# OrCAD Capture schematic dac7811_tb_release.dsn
size A
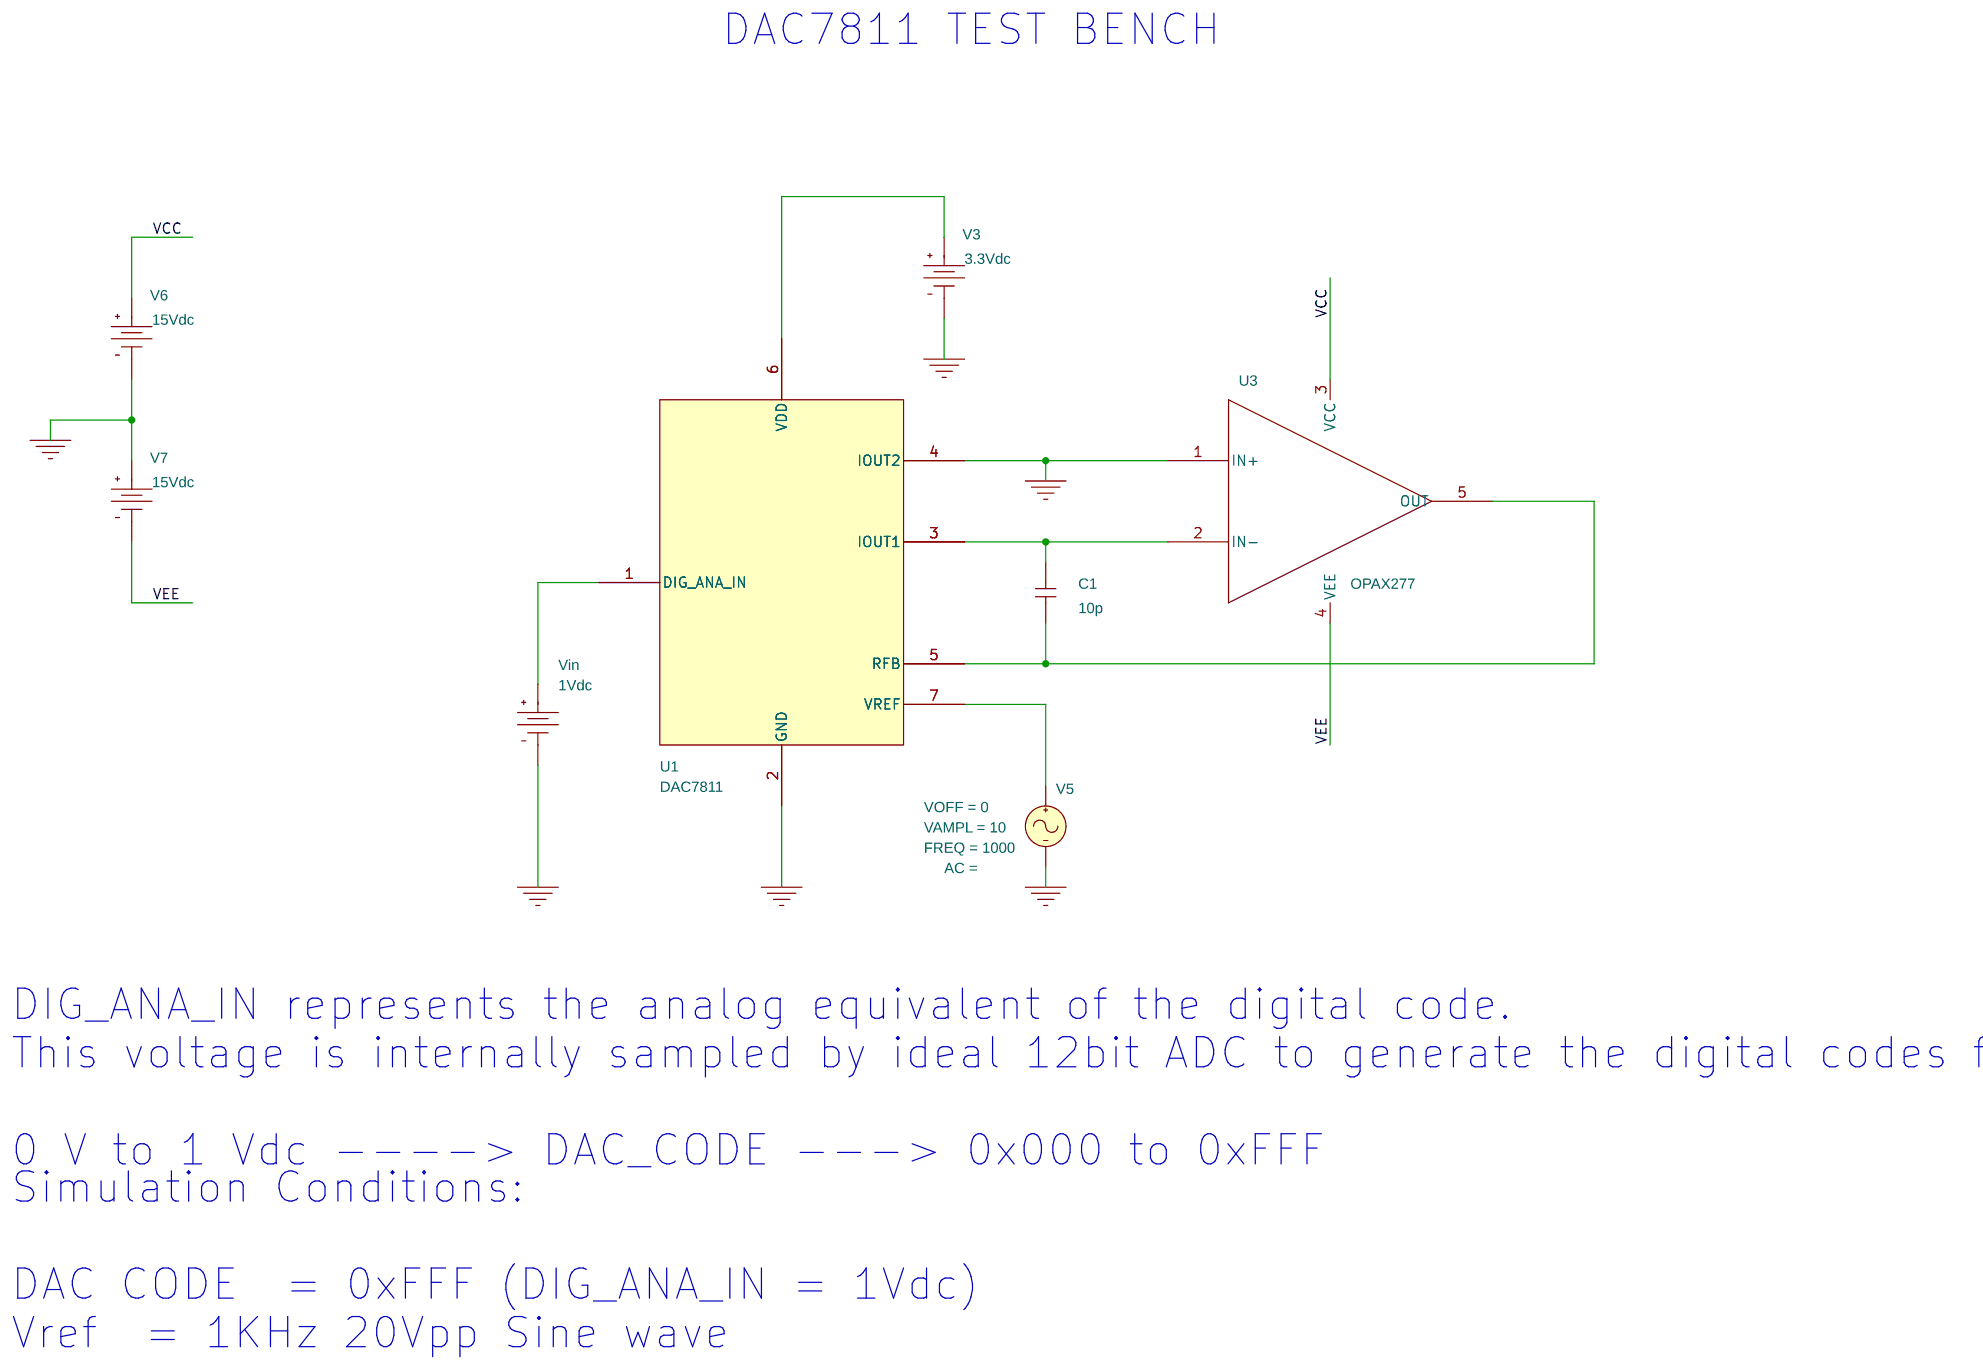
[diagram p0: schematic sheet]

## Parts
C1  10p  [RAD/CK05]
U1  DAC7811
U3  OPAX277
V3  VDC
V5  VSIN
V6  VDC
V7  VDC
Vin  VDC

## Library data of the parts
C1 = C
U1 = DAC7811_1: PSpiceTemplate: X^@REFDES  %DIG_ANA_IN %GND %IOUT1 %IOUT2 %RFB %VDD %VREF @MODEL
U3 = OPAX277_0
V3 = VDC: DC: 3.3Vdc
V5 = VSIN: FREQ: 1000; VAMPL: 10; VOFF: 0
V6 V7 = VDC: DC: 15Vdc
Vin = VDC: DC: 1Vdc

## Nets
VCC: U3.3(VCC) V6.0(+)
VEE: U3.4(VEE) V7.1(-)
0: U1.2(GND) U1.4(IOUT2) U3.1(IN+) V3.1(-) V5.2(-) V6.1(-) V7.0(+) Vin.1(-)
N02830: U1.6(VDD) V3.0(+)
N03018: C1.1 U1.5(RFB) U3.5(OUT)
N03030: C1.2 U1.3(IOUT1) U3.2(IN-)
N03042: U1.1(DIG_ANA_IN) Vin.0(+)
N03106: U1.7(VREF) V5.1(+)

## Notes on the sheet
- DAC7811 TEST BENCH
- DIG_ANA_IN represents the analog equivalent of the digital code.
  This voltage is internally sampled by ideal 12bit ADC to generate the digital codes for the DAC.
  0 V to 1 Vdc ----> DAC_CODE ---> 0x000 to 0xFFF
- Simulation Conditions:
  DAC CODE  = 0xFFF (DIG_ANA_IN = 1Vdc)
  Vref  = 1KHz 20Vpp Sine wave
